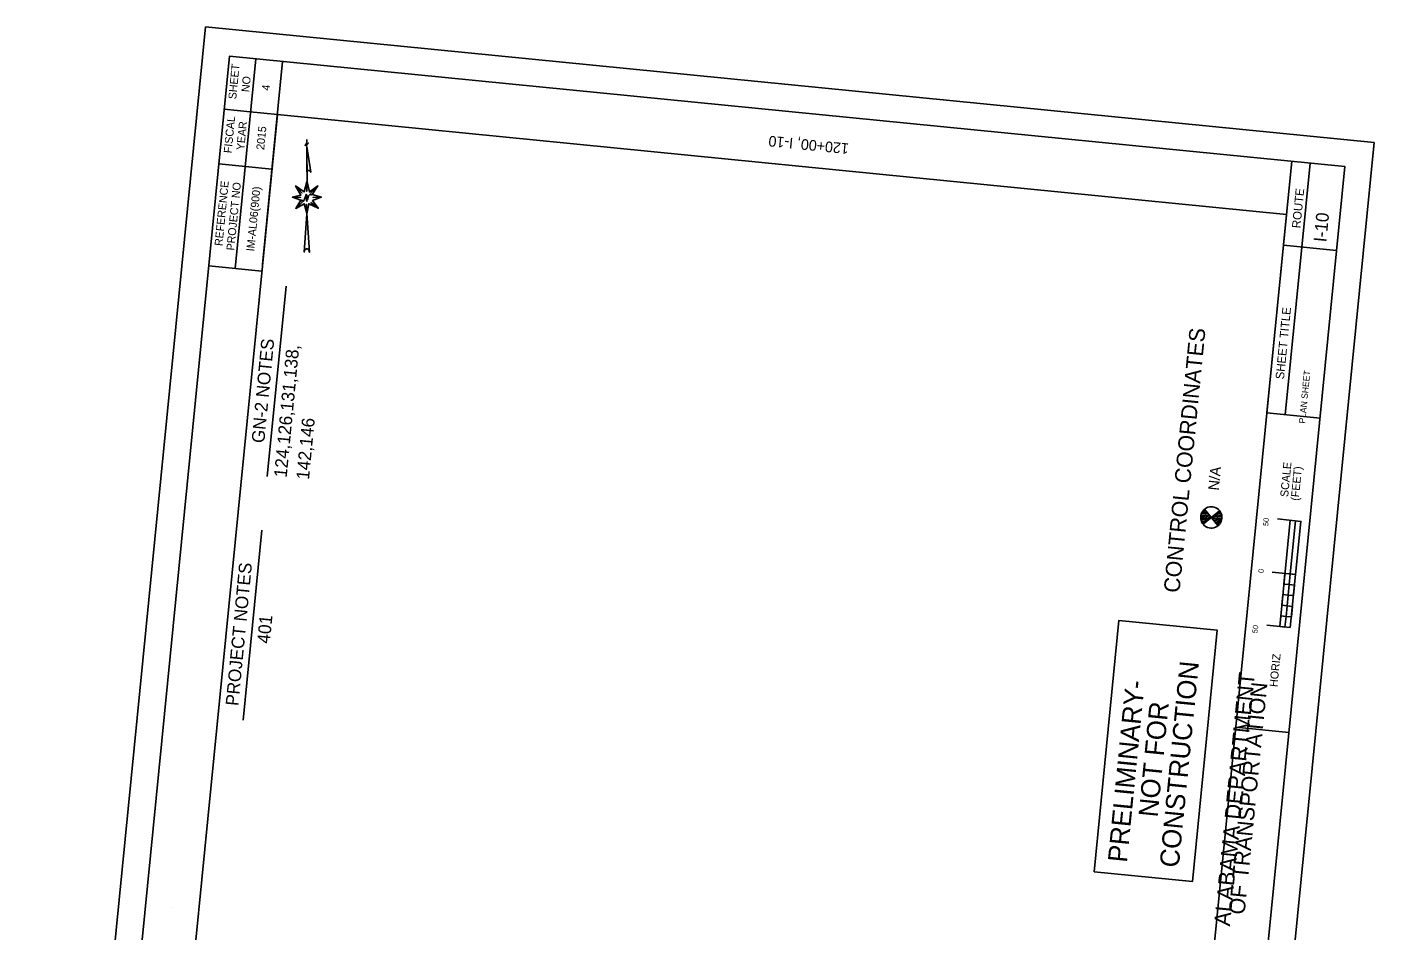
# Model space of a CAD drawing. Extents: x 1796928 to 1798191, y 245238 to 247038.
# Drawn here: x 1796928 to 1798191, y 246192 to 247038 of the extents above; entities that cross this region are included whole.
import ezdxf

# ---------------------------------------------------------------- set-up
doc = ezdxf.new("R2010")
doc.units = 0
for name, color, linetype in [('1', 7, 'Continuous'), ('ANNO-SHT', 7, 'Continuous'), ('ANNO-SYMB', 7, 'Continuous'), ('ANNO-TXT', 7, 'Continuous'), ('CL-CNST', 7, 'Continuous'), ('CLOSURE', 7, 'Continuous'), ('Default', 7, 'Continuous'), ('DRAINAGE', 7, 'Continuous'), ('Level 1', 7, 'Continuous'), ('Level 31', 7, 'Continuous'), ('Level 37', 7, 'Continuous'), ('Level 45', 7, 'Continuous'), ('Level 57', 7, 'Continuous'), ('Level 6', 7, 'Continuous'), ('Level 62', 7, 'Continuous'), ('SHT-BDR', 7, 'Continuous'), ('SHT-BNDRY', 7, 'Continuous')]:
    doc.layers.add(name, color=color, linetype=linetype)

# ---------------------------------------------------------------- blocks, each defined once
blk = doc.blocks.new('SC47208')
at = {"layer": 'Level 1'}
blk.add_line((0, 0), (0, 0), dxfattribs=at)
blk = doc.blocks.new('POINT_DISPLAY')
at = {"layer": 'Default'}
blk.add_line((0, 0), (0, 0), dxfattribs=at)

msp = doc.modelspace()

# ---------------------------------------------------------------- linework, layer by layer
at = {"layer": '1'}
msp.add_lwpolyline([(1797928.2, 246246.4), (1797951.4, 246481.7), (1798043.6, 246472.6), (1798020.3, 246237.3)], close=True, dxfattribs=at)
at = {"layer": 'ANNO-SYMB'}
for p, q in [((1798122, 246574.6), (1798100.1, 246576.8)), ((1798112, 246575.6), (1798102.2, 246476.1)), ((1798122, 246574.6), (1798112.1, 246475.1)), ((1798122, 246574.6), (1798117, 246575.1)), ((1798122, 246574.6), (1798117, 246575.1)), ((1798122, 246574.6), (1798117, 246575.1)), ((1798117, 246524.9), (1798095.2, 246527.1)), ((1798117, 246524.9), (1798095.2, 246527.1)), ((1798117, 246524.9), (1798095.2, 246527.1)), ((1798112.1, 246525.4), (1798107.1, 246525.9)), ((1798112.1, 246525.4), (1798107.1, 246525.9)), ((1798112.1, 246525.4), (1798107.1, 246525.9)), ((1798112.1, 246525.4), (1798110.1, 246505.5)), ((1798108.1, 246485.6), (1798103.2, 246486.1)), ((1798108.1, 246485.6), (1798103.2, 246486.1)), ((1798112.1, 246475.1), (1798090.2, 246477.3))]:
    msp.add_line(p, q, dxfattribs=at)
for points in [[(1798112.1, 246525.4), (1798117, 246575.1), (1798122, 246574.6), (1798117, 246524.9)], [(1798106.1, 246515.9), (1798107.1, 246525.9), (1798112.1, 246525.4), (1798111.1, 246515.4)], [(1798104.1, 246496), (1798105.1, 246506), (1798110.1, 246505.5), (1798109.1, 246495.5)], [(1798110.1, 246505.5), (1798111.1, 246515.4), (1798116.1, 246514.9), (1798115.1, 246505)], [(1798108.1, 246485.6), (1798109.1, 246495.5), (1798114.1, 246495), (1798113.1, 246485.1)], [(1798102.2, 246476.1), (1798103.2, 246486.1), (1798108.1, 246485.6), (1798107.1, 246475.6)]]:
    msp.add_lwpolyline(points, close=True, dxfattribs=at)
at = {"layer": 'ANNO-TXT'}
for p, q in [((1798122.9, 246831.4), (1798130.7, 246910.1)), ((1798107.4, 246674.5), (1798122.9, 246831.4))]:
    msp.add_line(p, q, dxfattribs=at)
at = {"layer": 'CL-CNST'}
for p, q in [((1797153.6, 246616.6), (1797171.2, 246794.7)), ((1797131, 246388.3), (1797148.6, 246566.4))]:
    msp.add_line(p, q, dxfattribs=at)
at = {"layer": 'CLOSURE'}
for p, q in [((1798028.2, 246580), (1798028.1, 246578.5)), ((1798028.6, 246581.5), (1798028.2, 246580)), ((1798029.2, 246582.9), (1798028.6, 246581.5)), ((1798028.9, 246580.5), (1798036.9, 246579.7)), ((1798030, 246584.2), (1798029.2, 246582.9)), ((1798029.4, 246581.8), (1798035.7, 246581.2)), ((1798031, 246585.4), (1798030, 246584.2)), ((1798030.2, 246583.1), (1798034.5, 246582.7)), ((1798030.4, 246572), (1798045.7, 246584.6)), ((1798030.9, 246584.3), (1798033.3, 246584.1)), ((1798032.2, 246586.4), (1798031, 246585.4)), ((1798031.8, 246585.9), (1798044.3, 246570.6)), ((1798033.5, 246587.2), (1798032.2, 246586.4)), ((1798034.9, 246587.8), (1798033.5, 246587.2)), ((1798036.4, 246588.1), (1798034.9, 246587.8)), ((1798037.9, 246588.3), (1798036.4, 246588.1)), ((1798039.4, 246588.2), (1798037.9, 246588.3)), ((1798040.9, 246587.9), (1798039.4, 246588.2)), ((1798047.5, 246578.7), (1798039.5, 246579.5)), ((1798042.3, 246587.3), (1798040.9, 246587.9)), ((1798041, 246580.7), (1798047.3, 246580.1)), ((1798043.7, 246586.6), (1798042.3, 246587.3)), ((1798042.4, 246581.9), (1798046.7, 246581.5)), ((1798044.9, 246585.6), (1798043.7, 246586.6)), ((1798043.9, 246583.1), (1798046.2, 246582.9)), ((1798045.9, 246584.5), (1798044.9, 246585.6)), ((1798046.8, 246583.2), (1798045.9, 246584.5)), ((1798047.4, 246581.8), (1798046.8, 246583.2)), ((1798047.8, 246580.4), (1798047.4, 246581.8)), ((1798048, 246578.8), (1798047.8, 246580.4)), ((1798028.1, 246578.5), (1798028.1, 246577)), ((1798028.1, 246577), (1798028.5, 246575.5)), ((1798028.5, 246575.5), (1798029, 246574)), ((1798028.6, 246577.9), (1798036.6, 246577.1)), ((1798028.8, 246579.2), (1798047.3, 246577.4)), ((1798028.8, 246576.5), (1798035.1, 246575.9)), ((1798029, 246574), (1798029.8, 246572.7)), ((1798029.4, 246575.1), (1798033.7, 246574.7)), ((1798029.8, 246572.7), (1798030.7, 246571.5)), ((1798029.9, 246573.7), (1798032.2, 246573.5)), ((1798030.7, 246571.5), (1798031.8, 246570.5)), ((1798031.8, 246570.5), (1798033.1, 246569.6)), ((1798033.1, 246569.6), (1798034.5, 246568.9)), ((1798034.5, 246568.9), (1798036, 246568.5)), ((1798036, 246568.5), (1798037.5, 246568.3)), ((1798037.5, 246568.3), (1798039, 246568.3)), ((1798039, 246568.3), (1798040.5, 246568.6)), ((1798047.2, 246576.1), (1798039.3, 246576.8)), ((1798040.5, 246575.4), (1798046.8, 246574.8)), ((1798040.5, 246568.6), (1798042, 246569.1)), ((1798041.7, 246573.9), (1798046, 246573.5)), ((1798042, 246569.1), (1798043.3, 246569.8)), ((1798042.9, 246572.5), (1798045.2, 246572.2)), ((1798043.3, 246569.8), (1798044.6, 246570.7)), ((1798044.6, 246570.7), (1798045.6, 246571.8)), ((1798045.6, 246571.8), (1798046.5, 246573)), ((1798046.5, 246573), (1798047.3, 246574.4)), ((1798047.3, 246574.4), (1798047.7, 246575.8)), ((1798047.7, 246575.8), (1798048, 246577.3)), ((1798048, 246577.3), (1798048, 246578.8))]:
    msp.add_line(p, q, dxfattribs=at)
at = {"layer": 'Level 57'}
msp.add_line((1797190.8, 246932.2), (1797190.7, 246929.8), dxfattribs=at)
for points in [[(1797191.9, 246928.7), (1797191.8, 246928.6), (1797191.9, 246928.5), (1797192, 246928.6), (1797192, 246928.8), (1797191.7, 246928.8), (1797191.5, 246928.7), (1797191.3, 246928.5), (1797191.1, 246928.2), (1797191, 246927.8), (1797190.8, 246927.2), (1797190.7, 246927), (1797190.6, 246926.6), (1797190.6, 246927.2), (1797190.6, 246928.2), (1797190.4, 246928.8), (1797190.4, 246928.2), (1797190.6, 246926.6), (1797190.6, 246928.2), (1797190.4, 246928.8), (1797190.2, 246928.2), (1797189.9, 246927.2), (1797189.6, 246926.6), (1797189.3, 246926.6), (1797189.1, 246926.6), (1797189, 246926.6), (1797189, 246926.8), (1797189.1, 246926.9), (1797189.2, 246926.9), (1797189.1, 246926.7)], [(1797190.7, 246925.7), (1797194.4, 246901.6), (1797194.2, 246902.3), (1797194, 246902.6), (1797193.6, 246903), (1797193.1, 246903.2), (1797192.8, 246903.3), (1797192.4, 246903.3), (1797192, 246903.3), (1797191.8, 246903.2), (1797191.4, 246903), (1797191.1, 246902.8), (1797190.9, 246902.5), (1797190.8, 246902.2), (1797190.7, 246902.1), (1797190.7, 246925.5), (1797190.9, 246892.6)], [(1797190.8, 246892.6), (1797190.6, 246883.7), (1797190.8, 246892.7), (1797188.1, 246883.1), (1797180.2, 246888.7), (1797186.3, 246882), (1797180.2, 246888.7), (1797185.1, 246880.1), (1797177.1, 246878.2), (1797184.8, 246878), (1797177.3, 246878.3), (1797185, 246875.5), (1797180.4, 246867.7), (1797186.2, 246873.4), (1797180.4, 246867.7), (1797188.3, 246872), (1797190.6, 246863.1), (1797190.5, 246871.5), (1797190.6, 246862.9), (1797192.6, 246871.9), (1797201.6, 246867.8), (1797192.5, 246871.9), (1797190.6, 246862.7), (1797188.3, 246826.7), (1797188.5, 246827.8), (1797188.8, 246828.6), (1797189.3, 246829.1), (1797189.9, 246829.6), (1797190.4, 246829.7), (1797191.1, 246829.7), (1797191.6, 246829.5), (1797192.1, 246829.2), (1797192.5, 246828.7), (1797192.9, 246828), (1797193, 246827.5), (1797193.2, 246826.6), (1797190.7, 246863.2), (1797192.5, 246872), (1797201.4, 246867.8), (1797194.6, 246873.1), (1797201.3, 246868), (1797196.1, 246875), (1797204.1, 246878.1), (1797196.5, 246878), (1797204.4, 246878.1), (1797195.6, 246880.8), (1797201.1, 246888.7), (1797194.6, 246882.3), (1797201.1, 246888.7), (1797193.1, 246883.1), (1797190.9, 246892.5)], [(1797194.6, 246880.6), (1797194.4, 246880.4), (1797194.7, 246880.2), (1797194.9, 246880.5), (1797194.8, 246880.9), (1797194.7, 246881), (1797194, 246880.9), (1797193.4, 246880.7), (1797192.4, 246879.4), (1797192.3, 246879), (1797191.9, 246877.8), (1797191.5, 246876.5), (1797191, 246875.7), (1797190.8, 246874.3), (1797190.8, 246876), (1797190.6, 246878.3), (1797190.5, 246879.5), (1797190, 246880.9), (1797190, 246879.2), (1797190.3, 246876.9), (1797190.5, 246875.5), (1797190.8, 246874.3), (1797190.8, 246876.4), (1797190.6, 246879.5), (1797190, 246880.9), (1797189.7, 246879.4), (1797189.1, 246877.8), (1797188.8, 246877.2), (1797188.5, 246876.3), (1797188.1, 246875.6), (1797187.8, 246875.1), (1797187.6, 246874.5), (1797186.8, 246874.1), (1797186.1, 246874.3), (1797185.9, 246874.5), (1797185.8, 246875.2), (1797186.2, 246875.5), (1797186.5, 246875.2), (1797186.3, 246874.9)]]:
    msp.add_lwpolyline(points, dxfattribs=at)
at = {"layer": 'Level 6'}
for p, q in [((1797142.9, 247007.8), (1797123.5, 246811.5)), ((1797168, 247005.4), (1797149.2, 246815)), ((1797137.6, 246958.1), (1797113.4, 246960.5)), ((1797137.6, 246958.1), (1797163.1, 246955.6)), ((1797133.2, 246906.8), (1797108.3, 246909.3)), ((1798113.4, 246911.8), (1798090.1, 246676.3)), ((1797133.2, 246906.8), (1797158, 246904.4)), ((1797098.9, 246813.9), (1797148.6, 246809))]:
    msp.add_line(p, q, dxfattribs=at)
at = {"layer": 'Level 62'}
msp.add_lwpolyline([(1798023.1, 245237.6), (1798190.5, 246929.3), (1797095.9, 247037.6), (1796928.5, 245345.9)], close=True, dxfattribs=at)
at = {"layer": 'SHT-BDR'}
msp.add_lwpolyline([(1797960.8, 245369.3), (1798108.5, 246862), (1797163.1, 246955.6), (1797015.4, 245462.9)], close=True, dxfattribs=at)
at = {"layer": 'SHT-BNDRY'}
for p, q in [((1798155.4, 246828.2), (1798105.6, 246833.1)), ((1798139.9, 246671.3), (1798090.1, 246676.3)), ((1798110.8, 246376.8), (1798060.9, 246381.7))]:
    msp.add_line(p, q, dxfattribs=at)
msp.add_lwpolyline([(1798004.4, 245302.2), (1798163.2, 246906.9), (1797118.3, 247010.3), (1796959.5, 245405.6)], close=True, dxfattribs=at)

# ---------------------------------------------------------------- block references
at = {"layer": 'CLOSURE', "xscale": 1.999999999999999, "yscale": 1.9999999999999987, "rotation": -5.5509635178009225}
msp.add_blockref('POINT_DISPLAY', (1798038.1, 246578.3), dxfattribs=at)
at = {"layer": 'DRAINAGE', "xscale": 1.0000020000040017, "yscale": 1.000002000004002, "rotation": -32.067534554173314}
msp.add_blockref('SC47208', (1797063.6, 246213.4), dxfattribs=at)
msp.add_blockref('SC47208', (1797063.6, 246213.4), dxfattribs=at)

# ---------------------------------------------------------------- texts
at = {"layer": '1'}
for s, p in [('CONSTRUCTION', (1798007.5, 246249.8)), ('PRELIMINARY-', (1797959, 246254.6)), ('NOT FOR', (1797987.7, 246297))]:
    msp.add_text(s, height=18, rotation=84.3491, dxfattribs=at).set_placement(p)
at = {"layer": 'ANNO-SHT'}
for s, height, rotation, p in [('4', 7.45, 84.3491, (1797155.9, 246977.7)), ('2015', 7.45, 84.3491, (1797150.7, 246922.2)), ('120+00, I-10', 10, 174.3491, (1797698.9, 246928.4)), ('IM-AL06(900)', 7.449, 84.3491, (1797141.4, 246827.2)), ('  I-10  ', 12, 84.3491, (1798144.9, 246826.8)), ('               PLAN SHEET               ', 6, 84.3491, (1798122.7, 246632.7))]:
    msp.add_text(s, height=height, rotation=rotation, dxfattribs=at).set_placement(p)
at = {"layer": 'ANNO-SYMB'}
for s, height, p in [('SCALE', 7.5, (1798110, 246597.1)), ('(FEET)', 7.5, (1798119.9, 246593.6)), (' 50', 5, (1798091.2, 246568.1)), ('0', 5, (1798087, 246526)), ('0', 5, (1798087, 246526)), ('0', 5, (1798087, 246526)), (' 50', 5, (1798081.2, 246467.7)), ('HORIZ', 7.5, (1798100, 246419.2))]:
    msp.add_text(s, height=height, rotation=84.4063, dxfattribs=at).set_placement(p)
at = {"layer": 'ANNO-TXT'}
for s, height, p in [('ROUTE', 8, (1798121.5, 246848.8)), ('SHEET TITLE', 8, (1798106.1, 246707.3)), ('ALABAMA DEPARTMENT', 15, (1798055.5, 246195)), ('OF TRANSPORTATION', 15, (1798069.2, 246205.8))]:
    msp.add_text(s, height=height, rotation=84.3491, dxfattribs=at).set_placement(p)
at = {"layer": 'Level 31'}
msp.add_text('N/A', height=10, rotation=84.3491, dxfattribs=at).set_placement((1798045, 246603.2))
at = {"layer": 'Level 37'}
for s, p in [('GN-2 NOTES', (1797150.8, 246647.5)), ('124,126,131,138,', (1797171.8, 246615.2)), ('142,146', (1797192.7, 246613.2)), ('PROJECT NOTES', (1797126.5, 246401.4)), ('401', (1797156, 246459.7))]:
    msp.add_text(s, height=12, rotation=84.503, dxfattribs=at).set_placement(p)
at = {"layer": 'Level 45'}
msp.add_text('CONTROL COORDINATES', height=14.899, rotation=84.3491, dxfattribs=at).set_placement((1798008.2, 246507.2))
at = {"layer": 'Level 6'}
for s, p in [('SHEET', (1797124.5, 246969.6)), ('NO', (1797136.7, 246976.3)), ('FISCAL', (1797120.2, 246919.1)), ('YEAR', (1797132, 246921.9)), ('REFERENCE', (1797111.6, 246832.2)), ('PROJECT NO', (1797122.7, 246828))]:
    msp.add_text(s, height=7.44, rotation=84.3491, dxfattribs=at).set_placement(p)

doc.saveas('drawing.dxf')
